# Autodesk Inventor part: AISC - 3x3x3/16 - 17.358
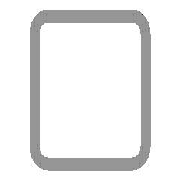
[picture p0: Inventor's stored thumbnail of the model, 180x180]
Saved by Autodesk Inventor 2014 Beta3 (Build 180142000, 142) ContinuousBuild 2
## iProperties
IsCustomPart: 1
Created: 2011-11
Part Number: AISC - 3x3x3/16 - 17.358
Material: Steel, Mild
Description: Tube
Document SubType Name: Modeling
Standard: ANSI
Designer: Thom Tremblay
Standards Organization: ANSI
Language: en-US
Size Designation: 3x3x3/16
Categories: <MemberInstance><Categories><Category DisplayName="Structural Shapes" InternalName="089c4875-fa83-4c05-b084-43b9cc11f5ed" Mnemonic="GRDR"><CategoryParameter Dis
Stock Number: 3x3x3/16
Density: 7.86 g/cm^3
Appearance: Steel
_CCFamilyMember: 9
_CCFamilyDisplayName: ANSI AISC (Square) - Tube
_FrameMemberDoc: Frame Member File
_Version: 15.0.0
_GetPNFromCC: 1
G_L: 17.358 in
G_W: 3.000 in
G_H: 3.000 in
+6CAF9BDE-E026-4916-956A-E37FFE89AF66+CUTDETAIL3: Cut
+DEDAD3BB-7673-4315-A3F7-EF655C76C181+CUTDETAIL4: Cut
Author: Thom Tremblay
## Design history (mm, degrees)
node "Start plane"
node "End plane"
node "Driven Length"
  sketch "Sketch3"
    geometry: L1 (0, 0)-(10, 0) reference
    constraints: 2 end point, 1 horizontal
  workplane "Work Plane3"
  sketch "Sketch4"
    geometry: L1 (-2, 0)-(12, 0) reference; L2 (-53.343, 440.904)-(53.343, 440.904) reference
    dimensions: "d19" = 440.90386 distance between parallel lines of L1 L2 (derived)
sketch "Sweep Path"
  geometry: L1 through (609.6, 0) direction (-1, -0); 1 other entity
  constraints: 5 horizontal
node "Orientation Work Plane"
feature "Body" dims "d20" = 0
workplane "Work Plane7"
sketch "Sketch7"
  geometry: L1 (-38.6, 38.6)-(38.6, 38.6); L2 (-38.6, -38.6)-(38.6, -38.6)
  constraints: 4 end point
feature "LoftSrf3" sketch "Sketch7" dims "d29" = 0, "d30" = 90 deg, "d31" = 0, "d32" = 90 deg
split "Split3"
workplane "Work Plane8"
sketch "Sketch8"
  geometry: L1 (-38.6, 38.6)-(38.6, 38.6); L2 (-38.6, -38.6)-(38.6, -38.6)
  constraints: 4 end point
feature "LoftSrf4" sketch "Sketch8" dims "d33" = 0, "d34" = 90 deg, "d35" = 0, "d36" = 90 deg
split "Split4"
workplane "Work Plane9"
sketch "Sketch9"
  geometry: L1 (-38.6, 44.506)-(38.6, 44.506); L2 (-38.6, -44.506)-(38.6, -44.506)
  constraints: 4 end point
feature "LoftSrf5" sketch "Sketch9" dims "d37" = 0, "d38" = 90 deg, "d39" = 0, "d40" = 90 deg
split "Split5"
workplane "Work Plane10"
sketch "Sketch10"
  geometry: L1 (-38.6, 44.506)-(38.6, 44.506); L2 (-38.6, -44.506)-(38.6, -44.506)
  constraints: 4 end point
feature "LoftSrf6" sketch "Sketch10" dims "d41" = 0, "d42" = 90 deg, "d43" = 0, "d44" = 90 deg
split "Split6"
body "Solid1"
sketch "Sketch"
  geometry: L1 (-38.1, -28.575)-(-38.1, 28.575); L2 (-28.575, 38.1)-(28.575, 38.1); L3 (38.1, 28.575)-(38.1, -28.575); L4 (28.575, -38.1)-(-28.575, -38.1); L5 (-28.575, 33.337)-(28.575, 33.338); L6 (33.338, 28.575)-(33.338, -28.575); L7 (28.575, -33.337)-(-28.575, -33.338); L8 (-33.338, -28.575)-(-33.338, 28.575); L9 (0, 36.948)-(0, -36.948); L10 (-23.079, 0)-(23.079, 0); A1 r 9.525 centre (-28.575, -28.575) between (-38.1, -28.575) and (-28.575, -38.1); A2 r 9.525 centre (-28.575, 28.575) between (-28.575, 38.1) and (-38.1, 28.575); A3 r 9.525 centre (28.575, 28.575) between (38.1, 28.575) and (28.575, 38.1); A4 r 9.525 centre (28.575, -28.575) between (28.575, -38.1) and (38.1, -28.575); A5 r 4.763 centre (-28.575, 28.575) between (-28.575, 33.337) and (-33.338, 28.575); A6 r 4.763 centre (28.575, 28.575) between (33.338, 28.575) and (28.575, 33.338); A7 r 4.763 centre (28.575, -28.575) between (28.575, -33.337) and (33.338, -28.575); A8 r 4.763 centre (-28.575, -28.575) between (-33.338, -28.575) and (-28.575, -33.338)
  constraints: 20 end point, 16 point on circle, 8 centre point, 8 tangent, 4 parallel, 3 equal radius, 2 perpendicular, 7 other
  dimensions: "d10" = 76.2 distance between parallel lines of L2 L4 (= G_H); "d11" = 76.2 distance between parallel lines of L1 L3 (= G_W); "d12" = 4.7625 distance between parallel lines of L3 L6 (= G_T); "d15" = 38.1 distance between parallel lines of L2 L10 (= 0.5 x d10); "d16" = 38.1 distance between parallel lines of L9 L3 (= 0.5 x d11); "d17" = 9.525 radius of A1 (= G_IR)
body "Srf3"
body "Srf4"
body "Srf5"
body "Srf6"
other parameters: "G_W" = 76.2 [user parameter; used in 1 equation term], "G_H" = 76.2 [user parameter; used in 1 equation term], "G_T" = 4.7625 [user parameter; used in 1 equation term], "G_IR" = 9.525 [user parameter; used in 1 equation term], "G_L" = 440.90386 (= d19) [user parameter], "G_OFFSET_START" = 0 [user parameter; used in 1 equation term], "G_OFFSET_END" = 0 [user parameter; used in 1 equation term], "d13" = 0 (computed from G_OFFSET_START), "d14" = 440.90386 (= G_OFFSET_END + B_L), "B_L" = 440.90386 [user parameter; used in 1 equation term], "d18" = 90 deg
